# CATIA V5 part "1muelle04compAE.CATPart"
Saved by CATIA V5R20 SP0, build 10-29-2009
Part number: 1muelle04compAE
Revision: ANY
Definition: UNKNOWN
Nomenclature: 1muelle04compAE
Source: Unknown
Bounding box of the stored display mesh (mm): x -3.9 to 3.9, y -3.9 to 3.9, z -0.001 to 8.199
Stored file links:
  C:\Users\Utente\Desktop\IO LAVORO\3D X SITO CF\CUMSA\3D files BE\BE 041216\1muelle04compAE.CATPart
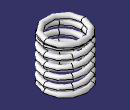
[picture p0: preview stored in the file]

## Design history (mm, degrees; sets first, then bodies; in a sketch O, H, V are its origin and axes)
Set1 "FacciaKO#NONE#104"
  DatumSurface1 "Sup104_1"
  DatumCurve1 "Crv104_1"
Set2 "FacciaKO#NONE#4710"
  DatumSurface2 "Sup4710_1"
  DatumCurve2 "Crv4710_1"
Body1 "Cortar-Extruir1" (main body)
  Solid1: solid without history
